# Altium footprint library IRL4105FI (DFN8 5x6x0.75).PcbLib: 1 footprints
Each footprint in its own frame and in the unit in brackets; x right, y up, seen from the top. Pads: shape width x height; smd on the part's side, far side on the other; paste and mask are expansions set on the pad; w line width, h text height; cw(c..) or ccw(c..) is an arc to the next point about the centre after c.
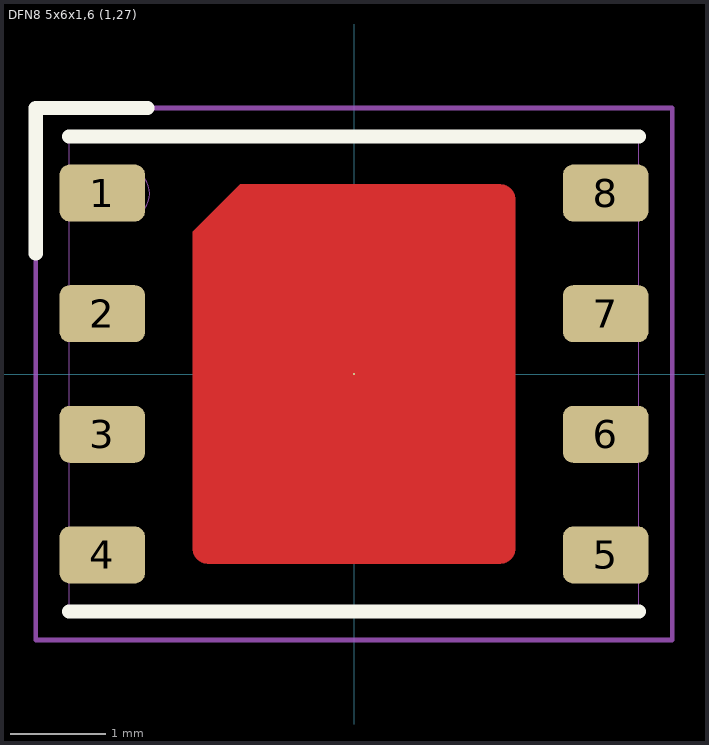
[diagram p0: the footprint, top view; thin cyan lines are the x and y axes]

## DFN8 5x6x1,6 (1,27) [mm]
height 1.7
pads (9):
  rrect35% 0.9x0.6 smd mask+0.05: 1(-2.65,1.905) 2(-2.65,0.635) 3(-2.65,-0.635) 4(-2.65,-1.905) 5(2.65,-1.905) 6(2.65,-0.635) 7(2.65,0.635) 8(2.65,1.905)
  round 0.025 smd: 9(0,0)
Top Layer:
  region: -1.2,2 -1.7,1.5 -1.7,-1.83 -1.7,-1.847 -1.694,-1.88 -1.681,-1.911 -1.662,-1.938 -1.638,-1.962 -1.611,-1.981 -1.58,-1.994 -1.547,-2 -1.53,-2 1.53,-2 1.547,-2 1.58,-1.994 1.61,-1.981 1.638,-1.962 1.662,-1.938 1.681,-1.911 1.693,-1.88 1.7,-1.847 1.7,-1.83 1.7,1.83 1.7,1.847 1.693,1.88 1.681,1.91 1.662,1.938 1.638,1.962 1.61,1.981 1.58,1.993 1.547,2 1.53,2
Top Overlay:
  lines w0.15: -3.35,1.27 -3.35,2.8 -2.175,2.8 ; -3,-2.5 3,-2.5 ; -3,2.5 3,2.5
Top Assembly:
  circle w0: c-2.4,1.9 r0.25
  lines w0: -3,-2.5 3,-2.5 3,2.5 -3,2.5 -3,-2.5
  text ".Designator" at -2.618,-0.355 h1.52
Top Courtyard:
  lines w0.05: -3.35,-2.8 3.35,-2.8 3.35,2.8 -3.35,2.8 -3.35,-2.8
3D body "DFN8 5x6x0,75 (1,27).STEP": height 0.75, standoff 0, extent -3,-2.499 3,2.499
